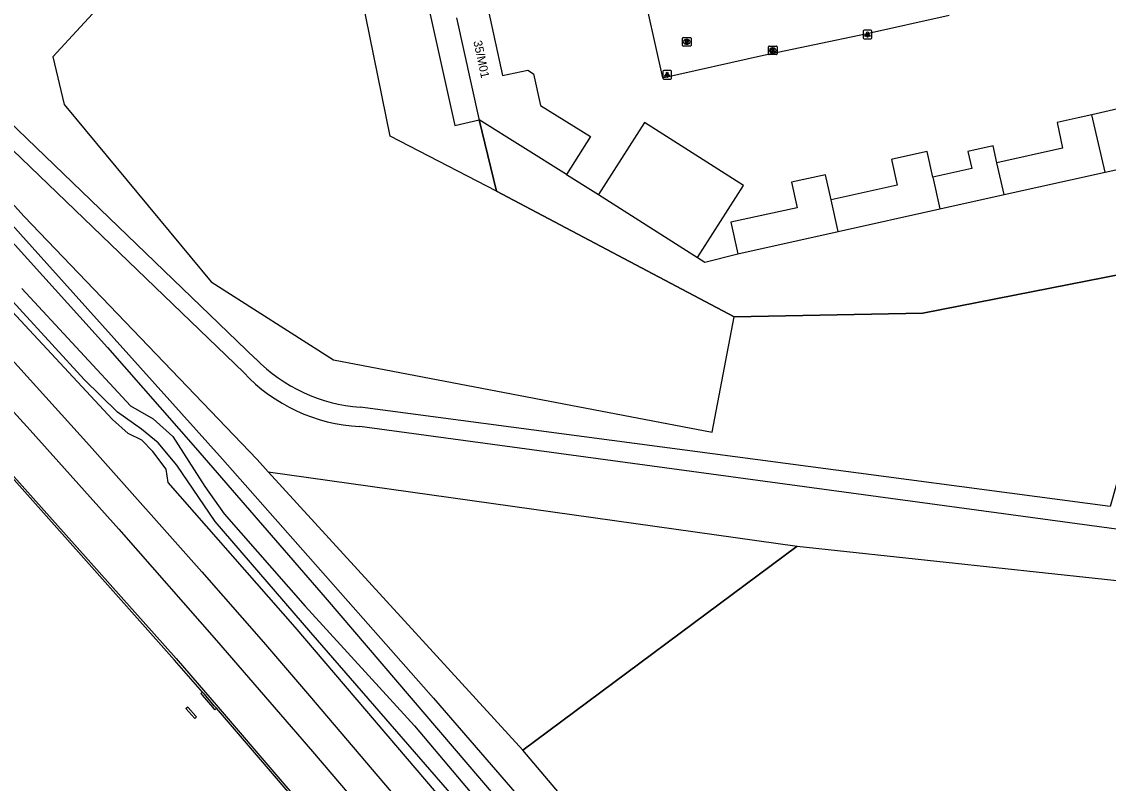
# Model space of a CAD drawing. Extents: x 164494 to 166241, y 382475 to 384494.
# Drawn here: x 164592.4 to 164719.3, y 383289.9 to 383378.9 of the extents above; entities that cross this region are included whole.
import ezdxf

# ---------------------------------------------------------------- set-up
doc = ezdxf.new("R2010")
doc.units = 0
for name, color, linetype in [('IMGEO_Geluidsscherm', 7, 'Continuous'), ('IMGEO_Grasland_agrarisch', 7, 'Continuous'), ('IMGEO_Grasland_overig', 7, 'Continuous'), ('IMGEO_Greppel_droge_sloot', 7, 'Continuous'), ('IMGEO_Groenvoorziening', 7, 'Continuous'), ('IMGEO_Hek', 7, 'Continuous'), ('IMGEO_Kolk', 7, 'Continuous'), ('IMGEO_Lichtpunt', 7, 'Continuous'), ('IMGEO_Loofbos', 7, 'Continuous'), ('IMGEO_Muur', 7, 'Continuous'), ('IMGEO_Pand', 7, 'Continuous'), ('IMGEO_Pand_nummerreeks', 7, 'Continuous'), ('IMGEO_Rijbaan_lokaal_open', 7, 'Continuous'), ('IMGEO_Rioolput', 7, 'Continuous'), ('IMGEO_Spoor', 7, 'Continuous'), ('IMGEO_Spoorbaan_halfverhard', 7, 'Continuous'), ('IMGEO_Voetpad_halfverhard', 7, 'Continuous')]:
    doc.layers.add(name, color=color, linetype=linetype)

msp = doc.modelspace()

# ---------------------------------------------------------------- linework, layer by layer
at = {"layer": 'IMGEO_Geluidsscherm'}
for points in [[(164630.07, 383281.29), (164615.17, 383298.69), (164614.96, 383298.93), (164613.72, 383300.37), (164613.54, 383300.58), (164610.29, 383304.33), (164587.13, 383330.28), (164574.53, 383344.16), (164566.74, 383352.48), (164549.76, 383370.16), (164548.93, 383371.03)], [(164549.11, 383371.2), (164549.64, 383370.65), (164566.92, 383352.66), (164574.72, 383344.33), (164587.32, 383330.45), (164610.48, 383304.5), (164613.91, 383300.53), (164615.15, 383299.09), (164630.26, 383281.45)]]:
    msp.add_lwpolyline(points, dxfattribs=at)
at = {"layer": 'IMGEO_Grasland_agrarisch'}
for points in [[(164682.99, 383317.62), (164650.95, 383293.8)], [(164682.99, 383317.62), (164769.99, 383308.3), (164799.31, 383293.78)], [(164719.87, 383217.06), (164717.65, 383214.93), (164650.95, 383293.8)]]:
    msp.add_lwpolyline(points, dxfattribs=at)
at = {"layer": 'IMGEO_Grasland_overig'}
for points in [[(164647.55, 383282.94), (164626.21, 383307.54), (164615.02, 383320.51), (164610.54, 383327.1), (164608.36, 383329.72), (164606.4, 383331.31), (164603.63, 383333.3), (164599.73, 383337.1), (164573.23, 383366.01), (164564.61, 383375.25), (164563.26, 383378.23), (164561.83, 383379.9), (164560.02, 383381.18), (164558.26, 383382.3), (164545.79, 383394.47), (164542.36, 383398.36), (164541.65, 383399.83), (164541.79, 383400.75), (164542.66, 383401.76), (164543.36, 383402.36), (164545.22, 383402.96), (164546.47, 383402.54)], [(164592.43, 383347.75), (164605.12, 383334.04), (164607.77, 383332.52), (164610.08, 383330.46), (164613.81, 383324.61), (164616.08, 383321.42), (164625.54, 383310.63), (164638.3, 383296.63), (164648.35, 383284.72)]]:
    msp.add_lwpolyline(points, dxfattribs=at)
at = {"layer": 'IMGEO_Greppel_droge_sloot'}
for points in [[(164569.83, 383378.65), (164569.16, 383378.04), (164569.02, 383377.8), (164569.2, 383377.18), (164573.97, 383371.95), (164585.53, 383359.56), (164602.43, 383340.85), (164612.71, 383329.12), (164627.85, 383311.62), (164654.34, 383280.65), (164673.17, 383257.81), (164689.1, 383238.16), (164711.71, 383211.78), (164717.14, 383205.62), (164718.96, 383203.68), (164725.76, 383197.02)], [(164569.83, 383378.65), (164587.45, 383359.42), (164615.87, 383327.81), (164640.51, 383299.89), (164650.27, 383288.61), (164668.17, 383267.71), (164695.9, 383235.58), (164717.07, 383210.84), (164719.59, 383207.25)]]:
    msp.add_lwpolyline(points, dxfattribs=at)
at = {"layer": 'IMGEO_Groenvoorziening'}
for points in [[(164621.22, 383326.32), (164619.91, 383327.76), (164592.72, 383356.14), (164551.1, 383402.1)], [(164629.72, 383393.71), (164608.98, 383388.87), (164596.05, 383374.78), (164597.4, 383369.21), (164614.57, 383348.52), (164628.84, 383339.41), (164673.05, 383330.95), (164675.64, 383344.43)], [(164656.07, 383361.04), (164659.78, 383358.72)], [(164647.88, 383359.09), (164675.64, 383344.43)], [(164671.36, 383351.36), (164672.21, 383350.82), (164676.05, 383351.79)], [(164675.64, 383344.43), (164697.66, 383344.85), (164729.61, 383351.14)], [(164650.95, 383293.8), (164621.22, 383326.32)], [(164621.22, 383326.32), (164682.99, 383317.62)], [(164615.17, 383298.69), (164614.98, 383298.52), (164614.77, 383298.77), (164613.53, 383300.21), (164613.35, 383300.42), (164613.54, 383300.58)], [(164611.61, 383298.67), (164611.81, 383298.86), (164611.88, 383298.79), (164612.78, 383297.78), (164612.85, 383297.7), (164612.64, 383297.52), (164611.61, 383298.67)]]:
    msp.add_lwpolyline(points, dxfattribs=at)
at = {"layer": 'IMGEO_Hek'}
for points in [[(164532.13, 383417.14), (164546.47, 383402.54), (164553.05, 383395.84), (164567.11, 383381.49), (164568.81, 383379.76), (164569.83, 383378.65), (164587.45, 383359.42), (164615.87, 383327.81), (164640.51, 383299.89), (164650.27, 383288.61), (164668.17, 383267.71), (164695.9, 383235.58), (164717.07, 383210.84), (164719.59, 383207.25), (164720.92, 383205.36), (164724.31, 383199.68), (164725.76, 383197.02), (164733.06, 383188.3), (164749.68, 383168.56), (164783.15, 383128.36)], [(164647.88, 383359.09), (164645.86, 383367.42)], [(164675.64, 383344.43), (164647.88, 383359.09)], [(164729.61, 383351.14), (164697.66, 383344.85), (164675.64, 383344.43)], [(164650.95, 383293.8), (164682.99, 383317.62)], [(164682.99, 383317.62), (164769.99, 383308.3), (164799.31, 383293.78)], [(164719.87, 383217.06), (164717.65, 383214.93), (164650.95, 383293.8)]]:
    msp.add_lwpolyline(points, dxfattribs=at)
at = {"layer": 'IMGEO_Kolk'}
for p, q in [((164679.65, 383375.13), (164679.65, 383375.98)), ((164679.72, 383376.05), (164680.57, 383376.05)), ((164680.65, 383375.98), (164680.65, 383375.13)), ((164680.57, 383375.05), (164679.72, 383375.05)), ((164680.13, 383375.83), (164680.16, 383375.83)), ((164680.16, 383375.27), (164680.13, 383375.27))]:
    msp.add_line(p, q, dxfattribs=at)
for points in [[(164679.65, 383375.13), (164679.65, 383375.98)], [(164679.72, 383376.05), (164680.57, 383376.05)], [(164680.65, 383375.98), (164680.65, 383375.13)], [(164680.57, 383375.05), (164679.72, 383375.05)], [(164679.97, 383375.75), (164680.09, 383375.75), (164680.09, 383375.6), (164680.22, 383375.75), (164680.38, 383375.75), (164680.24, 383375.6), (164680.39, 383375.35), (164680.24, 383375.35), (164680.15, 383375.52), (164680.09, 383375.45), (164680.09, 383375.35), (164679.97, 383375.35), (164679.97, 383375.75)]]:
    msp.add_lwpolyline(points, dxfattribs=at)
for centre, start, end in [((164679.72, 383375.98), 91.552, 178.448), ((164679.72, 383375.98), 91.552, 178.448), ((164680.57, 383375.98), 1.552, 88.448), ((164680.57, 383375.98), 1.552, 88.448), ((164679.72, 383375.13), 181.552, 268.448), ((164679.72, 383375.13), 181.552, 268.448), ((164680.57, 383375.13), 271.552, 358.448), ((164680.57, 383375.13), 271.552, 358.448)]:
    msp.add_arc(centre, 0.0765, start, end, dxfattribs=at)
for centre, major_axis, ratio, start_param, end_param in [((164680.13, 383375.55), (-0.387, 0.002), 0.722429, 4.712389, 7.853982), ((164680.16, 383375.55), (-0.39, 0.002), 0.717154, 1.570796, 4.712389)]:
    msp.add_ellipse(centre, major_axis=major_axis, ratio=ratio, start_param=start_param, end_param=end_param, dxfattribs=at)
at = {"layer": 'IMGEO_Lichtpunt'}
for p, q in [((164690.7, 383377.81), (164690.7, 383377)), ((164690.7, 383377.81), (164690.7, 383377)), ((164691.61, 383377.9), (164690.8, 383377.9)), ((164691.61, 383377.9), (164690.8, 383377.9)), ((164691.7, 383377), (164691.7, 383377.81)), ((164691.7, 383377), (164691.7, 383377.81)), ((164690.8, 383376.9), (164691.61, 383376.9)), ((164690.8, 383376.9), (164691.61, 383376.9)), ((164667.32, 383373.11), (164667.32, 383372.3)), ((164667.32, 383373.11), (164667.32, 383372.3)), ((164668.22, 383373.2), (164667.41, 383373.2)), ((164668.22, 383373.2), (164667.41, 383373.2)), ((164667.41, 383372.2), (164668.22, 383372.2)), ((164667.41, 383372.2), (164668.22, 383372.2)), ((164668.32, 383372.3), (164668.32, 383373.11)), ((164668.32, 383372.3), (164668.32, 383373.11))]:
    msp.add_line(p, q, dxfattribs=at)
for points in [[(164691.08, 383377.47), (164691.12, 383377.44), (164690.93, 383377.18), (164690.89, 383377.21), (164691.08, 383377.47)], [(164691.18, 383377.42), (164691.23, 383377.42), (164691.23, 383377.1), (164691.18, 383377.1), (164691.18, 383377.42)], [(164691.29, 383377.44), (164691.33, 383377.47), (164691.51, 383377.21), (164691.48, 383377.18), (164691.29, 383377.44)], [(164667.69, 383372.77), (164667.73, 383372.74), (164667.55, 383372.48), (164667.51, 383372.51), (164667.69, 383372.77)], [(164667.8, 383372.72), (164667.84, 383372.72), (164667.84, 383372.4), (164667.8, 383372.4), (164667.8, 383372.72)], [(164667.91, 383372.74), (164667.94, 383372.77), (164668.13, 383372.51), (164668.09, 383372.48), (164667.91, 383372.74)]]:
    msp.add_lwpolyline(points, dxfattribs=at)
for centre in [(164691.2, 383377.6), (164667.82, 383372.9)]:
    msp.add_circle(centre, 0.0994, dxfattribs=at)
for centre, start, end in [((164690.8, 383377.81), 90, 180), ((164690.8, 383377.81), 90, 180), ((164691.61, 383377.81), 0, 90), ((164691.61, 383377.81), 0, 90), ((164690.8, 383377), 180, 270), ((164690.8, 383377), 180, 270), ((164691.61, 383377), 270, 0), ((164691.61, 383377), 270, 360), ((164667.41, 383373.11), 90, 180), ((164667.41, 383373.11), 90, 180), ((164667.41, 383372.3), 180, 270), ((164667.41, 383372.3), 180, 270), ((164668.22, 383373.11), 0, 90), ((164668.22, 383373.11), 0, 90), ((164668.22, 383372.3), 270, 0), ((164668.22, 383372.3), 270, 360)]:
    msp.add_arc(centre, 0.0946, start, end, dxfattribs=at)
at = {"layer": 'IMGEO_Loofbos'}
for points in [[(164629.47, 383427.84), (164643, 383366.76), (164645.86, 383367.42)], [(164647.88, 383359.09), (164635.47, 383365.51), (164629.72, 383393.71)], [(164645.86, 383367.42), (164647.88, 383359.09)]]:
    msp.add_lwpolyline(points, dxfattribs=at)
at = {"layer": 'IMGEO_Muur'}
for points in [[(164549.64, 383370.65), (164566.92, 383352.66), (164574.72, 383344.33), (164587.32, 383330.45), (164610.48, 383304.5), (164613.91, 383300.53), (164615.15, 383299.09), (164630.26, 383281.45)], [(164613.54, 383300.58), (164610.29, 383304.33), (164587.13, 383330.28), (164574.53, 383344.16), (164566.74, 383352.48), (164549.76, 383370.16)], [(164615.17, 383298.69), (164614.96, 383298.93), (164613.72, 383300.37), (164613.54, 383300.58)], [(164630.07, 383281.29), (164615.17, 383298.69)]]:
    msp.add_lwpolyline(points, dxfattribs=at)
at = {"layer": 'IMGEO_Pand'}
for points in [[(164646.95, 383380.15), (164648.59, 383372.6), (164651.54, 383373.24), (164652.2, 383372.82), (164653, 383369.13), (164658.84, 383365.48), (164656.07, 383361.04)], [(164643.2, 383379.34), (164645.82, 383367.57), (164645.86, 383367.42)], [(164730.27, 383364.31), (164729.55, 383367.57), (164722.13, 383365.92), (164721.44, 383368.96), (164717.41, 383368.04)], [(164656.07, 383361.04), (164645.86, 383367.42)], [(164671.36, 383351.36), (164676.72, 383359.76), (164665.15, 383367.11), (164659.78, 383358.72)], [(164717.41, 383368.04), (164715.83, 383367.68), (164713.34, 383367.12), (164714, 383364.11), (164706.33, 383362.41)], [(164718.95, 383361.32), (164717.41, 383368.04)], [(164698.82, 383360.74), (164698.16, 383363.72), (164694.14, 383362.83), (164694, 383362.8), (164694.67, 383359.8), (164686.96, 383358.08)], [(164706.33, 383362.41), (164705.87, 383364.41), (164702.94, 383363.74), (164703.39, 383361.76), (164698.82, 383360.74)], [(164718.95, 383361.32), (164730.37, 383363.86), (164730.27, 383364.31)], [(164707.17, 383358.7), (164706.33, 383362.41)], [(164686.96, 383358.08), (164686.31, 383361.03), (164682.34, 383360.14), (164682.98, 383357.17), (164675.25, 383355.5), (164676.05, 383351.79)], [(164698.82, 383360.74), (164699.64, 383357.03)], [(164707.17, 383358.7), (164718.95, 383361.32)], [(164659.78, 383358.72), (164671.36, 383351.36)], [(164687.79, 383354.39), (164686.96, 383358.08)], [(164699.64, 383357.03), (164707.17, 383358.7)], [(164687.79, 383354.39), (164699.64, 383357.03)], [(164676.05, 383351.79), (164687.79, 383354.39)]]:
    msp.add_lwpolyline(points, dxfattribs=at)
at = {"layer": 'IMGEO_Rijbaan_lokaal_open'}
msp.add_lwpolyline([(164658.35, 383412.42), (164658.44, 383412.04), (164659.43, 383407.62), (164662.09, 383395.82), (164664.65, 383384.06), (164667.26, 383372.36), (164679.05, 383374.99), (164690.96, 383377.5), (164700.75, 383379.68)], dxfattribs=at)
at = {"layer": 'IMGEO_Rioolput'}
for p, q in [((164669.6, 383376.12), (164669.6, 383376.97)), ((164669.67, 383377.05), (164670.52, 383377.05)), ((164670.52, 383376.05), (164669.67, 383376.05)), ((164670.08, 383376.83), (164670.11, 383376.83)), ((164670.11, 383376.27), (164670.08, 383376.27)), ((164670.6, 383376.97), (164670.6, 383376.12))]:
    msp.add_line(p, q, dxfattribs=at)
for points in [[(164669.6, 383376.12), (164669.6, 383376.97)], [(164669.67, 383377.05), (164670.52, 383377.05)], [(164670.52, 383376.05), (164669.67, 383376.05)], [(164670.18, 383376.75), (164669.93, 383376.75), (164669.93, 383376.35)], [(164669.93, 383376.35), (164670.06, 383376.35), (164670.06, 383376.51), (164670.07, 383376.51)], [(164670.11, 383376.67), (164670.06, 383376.67), (164670.06, 383376.59)], [(164670.06, 383376.59), (164670.11, 383376.59)], [(164670.11, 383376.48), (164670.19, 383376.35), (164670.32, 383376.35), (164670.26, 383376.47)], [(164670.6, 383376.97), (164670.6, 383376.12)]]:
    msp.add_lwpolyline(points, dxfattribs=at)
for centre, radius, start, end in [((164669.67, 383376.97), 0.0765, 91.552, 178.448), ((164669.67, 383376.97), 0.0765, 91.552, 178.448), ((164669.67, 383376.12), 0.0765, 181.552, 268.448), ((164669.67, 383376.12), 0.0765, 181.552, 268.448), ((164670.07, 383376.46), 0.0533, 26.0293, 88.6989), ((164670.12, 383376.57), 0.0964, 77.0061, 93.1865), ((164670.09, 383376.78), 0.19, 274.7715, 282.9687), ((164670.13, 383376.63), 0.0378, 276.6634, 79.6772), ((164670.18, 383376.64), 0.109, 350.3612, 89.416), ((164670.18, 383376.64), 0.112, 277.5842, 350.9817), ((164670.17, 383376.42), 0.108, 29.5134, 73.7905), ((164670.52, 383376.97), 0.0765, 1.552, 88.448), ((164670.52, 383376.97), 0.0765, 1.552, 88.448), ((164670.52, 383376.12), 0.0765, 271.552, 358.448), ((164670.52, 383376.12), 0.0765, 271.552, 358.448)]:
    msp.add_arc(centre, radius, start, end, dxfattribs=at)
for centre, major_axis, ratio, start_param, end_param in [((164670.08, 383376.55), (-0.387, 0.002), 0.722429, 4.712389, 7.853982), ((164670.11, 383376.55), (-0.39, 0.002), 0.717154, 1.570796, 4.712389)]:
    msp.add_ellipse(centre, major_axis=major_axis, ratio=ratio, start_param=start_param, end_param=end_param, dxfattribs=at)
at = {"layer": 'IMGEO_Spoor'}
for points in [[(164497.16, 383435.76), (164505.01, 383428.31), (164523.25, 383410.43), (164538.04, 383395.69), (164557.43, 383375.71), (164570.01, 383362.48), (164585.76, 383345.51), (164600.35, 383329.41), (164613.46, 383314.64), (164620.68, 383306.41), (164626.03, 383300.15), (164652.19, 383269.4), (164681.85, 383233.76), (164715.83, 383193.24), (164785.24, 383110.17), (164816.48, 383072.61), (164890.55, 382984.09), (164958.66, 382902.34), (164967.09, 382892.29)], [(164494.45, 383433), (164503, 383424.89), (164513.86, 383414.22), (164535.42, 383392.64), (164546.22, 383381.6), (164561.18, 383366.01), (164572.19, 383354.32), (164582.17, 383343.51), (164593.42, 383331.17), (164603.76, 383319.61), (164615.18, 383306.6), (164626.39, 383293.63), (164637.88, 383280.18), (164662.08, 383251.56), (164693.34, 383214.26), (164754.17, 383141.12), (164812.5, 383071.43), (164837.86, 383040.96), (164896.06, 382971.37), (164932.4, 382927.69), (164964.12, 382889.8)]]:
    msp.add_lwpolyline(points, dxfattribs=at)
at = {"layer": 'IMGEO_Spoorbaan_halfverhard'}
msp.add_lwpolyline([(164646.76, 383281.93), (164624.36, 383308.16), (164609.53, 383325.06), (164609.3, 383326.62), (164607.75, 383328.71), (164606.47, 383330.01), (164604.85, 383330.79), (164603.03, 383332.42), (164569.79, 383368.19), (164562.82, 383375.93), (164562.55, 383377.4), (164561.58, 383378.53), (164560, 383379.84), (164558.65, 383380.28), (164557.86, 383380.87), (164540.07, 383398.98), (164523.08, 383416.41), (164517.64, 383421.45)], dxfattribs=at)
at = {"layer": 'IMGEO_Voetpad_halfverhard'}
for points in [[(164618.37, 383337.91), (164576.81, 383377.91), (164569.8, 383384.91), (164551.1, 383402.1)], [(164619.75, 383339.53), (164579.08, 383378.67), (164570.46, 383387.39)], [(164729.41, 383346.58), (164724.34, 383335.2), (164721.02, 383327.49), (164719.54, 383322.28), (164631.97, 383333.88)], [(164777.24, 383312.13), (164759.03, 383314.37), (164631.9, 383331.6)]]:
    msp.add_lwpolyline(points, dxfattribs=at)
for centre, radius, start, end in [((164633.3, 383352.78), 18.95, 224.3626, 265.9855), ((164632.97, 383351.59), 20.02, 223.1266, 266.9221)]:
    msp.add_arc(centre, radius, start, end, dxfattribs=at)

# ---------------------------------------------------------------- texts
at = {"layer": 'IMGEO_Pand_nummerreeks'}
msp.add_text('35/M01', height=1, rotation=282.0777, dxfattribs=at).set_placement((164645.17, 383376.6))

doc.saveas('drawing.dxf')
